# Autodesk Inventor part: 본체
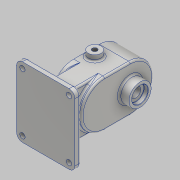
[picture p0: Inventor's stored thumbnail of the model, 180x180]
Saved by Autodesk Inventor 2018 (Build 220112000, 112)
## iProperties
Created: 2020-09
Part Number: 본체
Material: 알루미늄 6061
Document SubType Name: Modeling
Designer: home
Density: 2.7 g/cm^3
Appearance: 알루미늄 - 평지
Mass: 1440.45 g
Surface Area: 785.569 cm^2
Volume: 533.501 cm^3
Author: home
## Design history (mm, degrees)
sketch "스케치1"
  geometry: L1 (-40, 60)-(40, 60); L2 (50, 50)-(50, -50); L3 (40, -60)-(-40, -60); L4 (-50, -50)-(-50, 50); C1 r 4.5 at (-40, 50); C2 r 4.5 at (-40, -50); C3 r 4.5 at (40, -50); C4 r 4.5 at (40, 50); A1 r 10 centre (-40, 50) between (-40, 60) and (-50, 50); A2 r 10 centre (-40, -50) between (-50, -50) and (-40, -60); A3 r 10 centre (40, -50) between (40, -60) and (50, -50); A4 r 10 centre (40, 50) between (50, 50) and (40, 60); 6 further points
  constraints: 8 centre point, 8 end point, 8 point on circle, 8 tangent, 6 point on line, 4 coincident, 3 equal radius, 2 midpoint, 2 parallel, 1 horizontal, 1 horizontal alignment, 1 perpendicular, 1 vertical alignment
  dimensions: "d0" = 120 distance of point (-50, -60) point (-50, 60); "d1" = 100 distance of point (-50, 60) point (50, 60); "d2" = 10 radius of A1; "d3" = 9 diameter of C1; "d4" = 9 diameter of C2; "d5" = 9 diameter of C3; "d6" = 9 diameter of C4
extrude "돌출1" new body sketch "스케치1" stored distance "d7" = 10; taper "d8" = 0 deg
node "작업 평면1"
sketch "스케치2"
  geometry: L1 (-100, 0)-(0, 0) reference; L2 (-50, 0)-(-50, 90); L3 (-50, 90)-(-50, 112); L4 (-50, 90)-(-50, 68); L5 (-90, 112)-(-90, 68); L6 (-10, 112)-(-10, 68); A1 r 40 centre (-50, 68) between (-90, 68) and (-10, 68); A2 r 40 centre (-50, 112) between (-10, 112) and (-90, 112); 1 further point
  constraints: 10 end point, 4 point on circle, 4 vertical, 3 tangent, 2 centre point, 2 coincident, 1 midpoint, 1 point on line
  dimensions: "d10" = 90 distance of L2.start L2.end; "d11" = 22 distance of L2.end L3.end; "d12" = 22 distance of L2.end L4.end; "d19" = 40 radius of A2
extrude "돌출2" join sketch "스케치2" distance "d15" = 53; taper "d16" = 0 deg
sketch "스케치3"
  geometry: L1 (10, 112)-(10, 68) reference; L2 (90, 68)-(90, 112) reference; L3 (26, 112)-(26, 68); L4 (74, 112)-(74, 68); A1 r 40 centre (50, 68) between (10, 68) and (90, 68) reference; A2 r 40 centre (50, 112) between (90, 112) and (10, 112) reference; A3 r 24 centre (50, 112) between (74, 112) and (26, 112); A4 r 24 centre (50, 68) between (26, 68) and (74, 68); 1 further point
  constraints: 4 end point, 4 point on circle, 2 centre point, 2 coincident, 2 tangent, 2 vertical
  dimensions: "d20" = 24 radius of A3; "d21" = 24 radius of A4
extrude "돌출3" cut sketch "스케치3" distance "d22" = 29; taper "d23" = 0 deg
sketch "스케치5"
  geometry: L1 (-10, 112)-(-10, 68) reference; L2 (-90, 68)-(-90, 112) reference; C1 r 19 at (-50, 112); A1 r 40 centre (-50, 112) between (-10, 112) and (-90, 112) reference; A2 r 40 centre (-50, 68) between (-90, 68) and (-10, 68) reference; 1 further point
  constraints: 1 centre point, 1 coincident
  dimensions: "d29" = 38 diameter of C1
extrude "돌출4" join sketch "스케치5" distance "d30" = 17; taper "d31" = 0 deg
sketch "스케치6"
  geometry: L1 (33, 107)-(-20, 107) reference; L2 (9, 107)-(50, 107); L3 (9, 63)-(9, 107) reference; L4 (9, 107)-(9, 119.5); L5 (9, 107)-(9, 131) reference; L6 (9, 119.5)-(24, 119.5); L7 (50, 88)-(50, 126) reference; L8 (50, 107)-(50, 121.404); L9 (49.3, 121)-(43.2, 121); L10 (42.7, 120.5)-(42.7, 115.5); L11 (24, 119.5)-(24, 115.5); L12 (24, 115.5)-(42.7, 115.5); L13 (49.3, 121)-(50, 121.404); A1 r 0.5 centre (43.2, 120.5) between (43.2, 121) and (42.7, 120.5); 3 further points
  constraints: 18 end point, 7 point on line, 3 perpendicular, 2 point on circle, 2 tangent, 2 vertical, 1 centre point, 1 collinear, 1 midpoint
  dimensions: "d32" = 12.5 distance of L3.end L4.end; "d33" = 15 distance of L4.end L6.end; "d34" = 14 distance of L2.end point (50, 121); "d35" = 7.3 distance of point (50, 121) point (42.7, 121); "d36" = 4 distance of L6.end L11.end; "d37" = 0.5 radius of A1; "d38" = 0.7 distance of L9.start point (50, 121); "d39" = 150 deg angle of L9 L13
revolve "회전1" sketch "스케치6" stored, may be unused: angle "d41" = 90 deg
sketch "스케치7"
  geometry: L1 (26, 68)-(26, 112) reference; L2 (74, 112)-(74, 68) reference; C1 r 12.5 at (50, 112) reference; C2 r 12.5 at (50, 68); A1 r 24 centre (50, 68) between (26, 68) and (74, 68) reference; A2 r 24 centre (50, 112) between (74, 112) and (26, 112) reference; 1 further point
  constraints: 1 centre point, 1 coincident
  dimensions: "d42" = 25 diameter of C2
extrude "돌출5" cut sketch "스케치7" distance "d43" = 15; taper "d44" = 0 deg
sketch "스케치8"
  geometry: L1 (0, 0)-(0, 44) reference; L2 (0, 44)-(-53, 44) reference; L3 (-53, 0)-(-53, 44) reference; L4 (0, 0)-(-53, 0) reference; L5 (-53, 22)-(-39, 22); C1 r 11 at (-39, 22); 1 further point
  constraints: 2 end point, 1 centre point, 1 coincident, 1 horizontal, 1 midpoint
  dimensions: "d45" = 14 distance of L5.start L5.end; "d46" = 22 diameter of C1
extrude "돌출6" join sketch "스케치8" distance "d47" = 10; taper "d48" = 0 deg
sketch "스케치10"
  geometry: C1 r 11 at (0, 0) reference; 2 further points
  constraints: 1 coincident
hole "구멍2" sketch "스케치10" at (0, 0) diameter "d56" = 8.376; stored, may be unused: countersink angle "d60" = 90 deg, drill point angle "d62" = 118 deg; dims "d57" = 29, "d58" = 4, "d59" = 2, "d61" = 30
sketch "스케치11"
  geometry: L1 (26, 68)-(26, 112) reference; L2 (74, 112)-(74, 68) reference; L3 (10, 112)-(10, 68) reference; L4 (90, 68)-(90, 112) reference; L5 (19, 112)-(19, 68); L6 (81, 112)-(81, 68); L7 (50, 112)-(19, 112); L8 (50, 68)-(19, 68); L9 (50, 68)-(81, 68); L10 (50, 112)-(81, 112); L11 (50, 143)-(50, 37); C1 r 8.5 at (50, 112) reference; A1 r 24 centre (50, 68) between (26, 68) and (74, 68) reference; A2 r 24 centre (50, 112) between (74, 112) and (26, 112) reference; A3 r 40 centre (50, 68) between (10, 68) and (90, 68) reference; A4 r 40 centre (50, 112) between (90, 112) and (10, 112) reference; A5 r 31 centre (50, 112) between (19, 112) and (81, 112); A6 r 31 centre (50, 68) between (19, 68) and (81, 68); 3 further points
  constraints: 14 end point, 6 coincident, 6 point on circle, 2 centre point, 2 horizontal, 2 vertical, 1 parallel
  dimensions: "d63" = 62 diameter of A5; "d64" = 62 diameter of A6; "d65" = 24 distance between parallel lines of L2 L11
hole "구멍3" sketch "스케치11" at (19, 112), (19, 68), (50, 143), (50, 37), (81, 112), (81, 68) diameter "d66" = 4.134; stored, may be unused: countersink angle "d70" = 90 deg, drill point angle "d72" = 118 deg; dims "d67" = 10, "d68" = 4, "d69" = 2, "d71" = 12
chamfer "모따기1" distance "d73" = 1; stored, may be unused: second distance "d74" = 2, angle "d75" = 45 deg
sketch "스케치12"
  geometry: L1 (50, 50)-(50, -50) reference; L2 (50, 0)-(25, 0); L3 (25, 0)-(25, -40); L4 (25, -40)-(-12, -40); L5 (-12, -40)-(-12, 40); L6 (-12, 40)-(25, 40); L7 (25, 40)-(25, 0); 1 further point
  constraints: 12 end point, 5 perpendicular, 1 horizontal, 1 midpoint, 1 point on line
  dimensions: "d76" = 25 distance of L2.start L2.end; "d77" = 40 distance of L2.end L3.end; "d78" = 37 distance of L3.end L4.end; "d79" = 80 distance of L4.end L5.end
extrude "돌출7" join sketch "스케치12" stored distance "d80" = 10; taper "d81" = 0 deg
fillet "모깎기1" dims "d82" = 3
fillet "모깎기2" dims "d83" = 3
fillet "모깎기3" dims "d84" = 3
fillet "모깎기4" dims "d85" = 3
fillet "모깎기5" dims "d86" = 3
sketch "스케치13"
  geometry: L1 (-50, 50)-(-50, -50) reference; 2 further points
  constraints: 1 other
  dimensions: "d87" = 0 vertical distance of point (0, 0) point (-38, 0)
feature "엠보싱1" sketch "스케치13" dims "d0" = 120, "d89" = 0.5, "d90" = 0
node "솔리드1"
mirror "미러1"
mirror "미러2"
node "투영된 루프1"
node "투영된 루프3"
node "투영된 루프4"
node "투영된 루프5"
node "투영된 루프7"
node "투영된 루프8"
other parameters: "d9" = -17, "d17" = 48, "d18" = 48
